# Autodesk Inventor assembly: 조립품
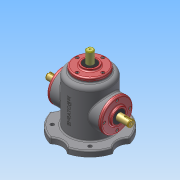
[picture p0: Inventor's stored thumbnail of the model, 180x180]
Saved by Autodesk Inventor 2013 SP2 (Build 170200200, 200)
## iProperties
Created: 2026-07
Part Number: 조립품
Document SubType Name: Assembly
Designer: a
Author: a
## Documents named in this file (12)
- C:\Users\a\Desktop\760703V1010\조립품.iam
- C:\Users\a\Desktop\760703V1010\본체.ipt
- C:\Users\a\Desktop\760703V1010\6각 구멍붙이 볼트 M4x10.ipt
- C:\Users\a\Desktop\760703V1010\깊은 홈 볼 베어링 6203.ipt
- C:\Users\a\Desktop\760703V1010\메인 베벨기어.ipt
- C:\Users\a\Desktop\760703V1010\메인 축.ipt
- C:\Users\a\Desktop\760703V1010\서브 베벨기어.ipt
- C:\Users\a\Desktop\760703V1010\서브 축.ipt
- C:\Users\a\Desktop\760703V1010\오일 실 17 32 8.ipt
- C:\Users\a\Desktop\760703V1010\커버.ipt
- C:\Users\a\Desktop\760703V1010\평행 키 4x4x14.ipt
- C:\Users\a\Desktop\760703V1010\평행 키 5x5x14.ipt
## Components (12 placed, 1 different names)
1. 6각 구멍붙이 볼트 M4x10:1
2. 6각 구멍붙이 볼트 M4x10:2
3. 6각 구멍붙이 볼트 M4x10:3
4. 6각 구멍붙이 볼트 M4x10:4
5. 6각 구멍붙이 볼트 M4x10:5
6. 6각 구멍붙이 볼트 M4x10:6
7. 6각 구멍붙이 볼트 M4x10:7
8. 6각 구멍붙이 볼트 M4x10:8
9. 6각 구멍붙이 볼트 M4x10:9
10. 6각 구멍붙이 볼트 M4x10:10
11. 6각 구멍붙이 볼트 M4x10:11
12. 6각 구멍붙이 볼트 M4x10:12
